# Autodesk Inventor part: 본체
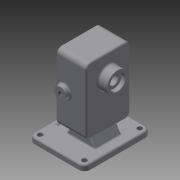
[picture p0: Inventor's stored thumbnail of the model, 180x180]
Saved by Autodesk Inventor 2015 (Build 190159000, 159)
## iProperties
Created: 2020-04
Part Number: 본체
Material: 일반
Document SubType Name: Modeling
Designer: CAD-08
Density: 1 g/cm^3
Appearance: 기본값
Author: CAD-08
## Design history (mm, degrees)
sketch "스케치1"
  geometry: L1 (50, -60)-(-50, -60); L2 (-50, -60)-(-50, 60); L3 (-50, 60)-(50, 60); L4 (50, 60)-(50, -60); L5 (50, -60)-(-50, 60); L6 (-50, -60)-(50, 60); 1 further point
  constraints: 12 end point, 2 midpoint, 2 parallel, 1 horizontal, 1 perpendicular
  dimensions: "d0" = 100 distance of L2.end L3.end; "d1" = 120 distance of L1.end L2.end
extrude "돌출1" new body sketch "스케치1" distance "d2" = 10; taper "d3" = 0 deg
fillet "모깎기1" dims "d4" = 10
sketch "스케치2"
  geometry: A1 r 10 centre (-40, 50) between (-40, 60) and (-50, 50) reference; A2 r 10 centre (-40, -50) between (-50, -50) and (-40, -60) reference; A3 r 10 centre (40, -50) between (40, -60) and (50, -50) reference; A4 r 10 centre (40, 50) between (50, 50) and (40, 60) reference; 1 further point
hole "구멍1" sketch "스케치2" at (-40, -50), (-40, 50), (40, -50), (40, 50) diameter "d5" = 9; stored, may be unused: countersink angle "d9" = 90 deg, drill point angle "d11" = 118 deg; dims "d6" = 6, "d7" = 4, "d8" = 2, "d10" = 8
sketch "스케치3"
  geometry: L1 (50, -50)-(50, 50) reference; L2 (-20, 24)-(33, 24); L3 (33, 24)-(33, -24); L4 (33, -24)-(-20, -24); L5 (-20, -24)-(-20, 24); L6 (0, 0)-(-20, 0)
  constraints: 10 end point, 2 horizontal, 2 parallel, 1 midpoint, 1 perpendicular, 1 other
  dimensions: "d12" = 48 distance of L4.end L2.start; "d13" = 53 distance of L3.end L4.end; "d14" = 17 distance between parallel lines of L1 L3
extrude "돌출2" join sketch "스케치3" distance "d15" = 50; taper "d16" = 0 deg
feature "면 기울기1" dims angle "d17" = 30 deg
feature "면 기울기2" dims angle "d18" = 30 deg
sketch "스케치5"
  geometry: L1 (-33, 10)-(-6.5, 55.899) reference; L2 (-6.5, 55.899)-(20, 10) reference; L3 (20, 10)-(50, 10) reference; L4 (50, 10)-(50, 0) reference; L5 (50, 0)-(-50, 0) reference; L6 (-50, 0)-(-50, 10) reference; L7 (-50, 10)-(-33, 10) reference; L8 (20, 30)-(-33, 30); L9 (-33, 30)-(-33, 150); L10 (-33, 150)-(20, 150); L11 (20, 150)-(20, 30); L12 (-6.5, 55.899)-(-6.5, 30); 1 further point
  constraints: 10 end point, 2 parallel, 1 horizontal, 1 midpoint, 1 perpendicular, 1 vertical, 1 other
  dimensions: "d26" = 120 distance of L10.end L8.start; "d27" = 53 distance of L9.end L10.end; "d28" = 150 distance between parallel lines of L5 L10
extrude "돌출4" join sketch "스케치5" stored distance "d29" = 80; taper "d30" = 0 deg
fillet "모깎기2" dims "d31" = 9
sketch "스케치7"
  geometry: A1 r 9 centre (9, 62) between (9, 71) and (0, 62) reference; A2 r 9 centre (9, 0) between (0, 0) and (9, -9) reference; A3 r 9 centre (111, 0) between (111, -9) and (120, 0) reference; A4 r 9 centre (111, 62) between (120, 62) and (111, 71) reference; 1 further point
hole "구멍2" sketch "스케치7" at (111, 62), (111, 0), (9, 62), (9, 0) diameter "d37" = 4.134; stored, may be unused: countersink angle "d41" = 90 deg, drill point angle "d43" = 118 deg; dims "d38" = 10, "d39" = 4, "d40" = 2, "d42" = 12
sketch "스케치8"
  geometry: C1 r 2.067 at (111, 62) reference; 2 further points
  constraints: 1 horizontal alignment
  dimensions: "d44" = 29 distance of C1.centre point (82, 62)
hole "구멍3" sketch "스케치8" at (82, 62) diameter "d45" = 4.134; stored, may be unused: countersink angle "d49" = 90 deg, drill point angle "d51" = 118 deg; dims "d46" = 10, "d47" = 4, "d48" = 2, "d50" = 12
sketch "스케치9"
  geometry: C1 r 2.067 at (9, 62) reference; 2 further points
  constraints: 1 horizontal alignment
  dimensions: "d52" = 29 distance of C1.centre point (38, 62)
hole "구멍4" sketch "스케치9" at (38, 62) diameter "d53" = 4.134; stored, may be unused: countersink angle "d57" = 90 deg, drill point angle "d59" = 118 deg; dims "d54" = 10, "d55" = 4, "d56" = 2, "d58" = 12
sketch "스케치12"
  geometry: L1 (9, 71)-(111, 71) reference; L2 (14, 31)-(106, 31); L3 (38, 7)-(82, 7); L4 (82, 55)-(38, 55); L5 (-30, -19)-(-30, 81) reference; A1 r 24 centre (38, 31) between (38, 55) and (38, 7); A2 r 24 centre (82, 31) between (82, 7) and (82, 55); 4 further points
  constraints: 8 end point, 6 point on circle, 4 tangent, 3 midpoint, 2 centre point, 2 point on line, 1 horizontal, 1 horizontal alignment, 1 parallel, 1 vertical alignment
  dimensions: "d71" = 24 radius of A2; "d72" = 92 distance of L2.start L2.end
extrude "돌출7" cut sketch "스케치12" distance "d73" = 29; taper "d74" = 0 deg
sketch "스케치13"
  geometry: L1 (-20, 141)-(-20, 39) reference; L2 (40, 0)-(-40, 0) reference; C1 r 11 at (-6, 90); 1 further point
  constraints: 1 centre point
  dimensions: "d75" = 22 diameter of C1; "d76" = 14 distance from line of L1 C1.centre; "d77" = 90 distance from line of L2 C1.centre
extrude "돌출8" join sketch "스케치13" distance "d78" = 8; taper "d79" = 0 deg
sketch "스케치14"
  geometry: C1 r 11 at (0, 0) reference; 1 further point
hole "구멍6" sketch "스케치14" at (0, 0) diameter "d80" = 8.376; stored, may be unused: countersink angle "d84" = 90 deg, drill point angle "d86" = 118 deg; dims "d81" = 20, "d82" = 4, "d83" = 2, "d85" = 27.3
sketch "스케치15"
  geometry: C1 r 12.5 at (82, 31); A1 r 24 centre (82, 31) between (82, 7) and (82, 55) reference; 1 further point
  constraints: 1 centre point, 1 coincident
  dimensions: "d87" = 25 diameter of C1
extrude "돌출9" cut sketch "스케치15" distance "d88" = 15; taper "d89" = 0 deg
sketch "스케치16"
  geometry: C1 r 12.5 at (38, 31); A1 r 24 centre (38, 31) between (38, 55) and (38, 7) reference; 1 further point
  constraints: 1 centre point, 1 coincident
  dimensions: "d90" = 25 diameter of C1
extrude "돌출10" cut sketch "스케치16" distance "d91" = 15; taper "d92" = 0 deg
sketch "스케치17"
  geometry: C1 r 12.5 at (0, 0) reference; C2 r 8.5 at (0, 0); 1 further point
  constraints: 1 centre point, 1 coincident
  dimensions: "d93" = 17 diameter of C2
extrude "돌출11" cut sketch "스케치17" stored distance "d94" = 15; taper "d95" = 0 deg
sketch "스케치18"
  geometry: C1 r 8.5 at (38, 31) reference; C2 r 19 at (38, 31); 1 further point
  constraints: 1 centre point, 1 coincident
  dimensions: "d96" = 38 diameter of C2
extrude "돌출12" join sketch "스케치18" distance "d97" = 17; taper "d98" = 0 deg
sketch "스케치19"
  geometry: C1 r 8.5 at (0, 0) reference; C2 r 19 at (0, 0) reference; C3 r 14 at (0, 0); 1 further point
  constraints: 1 centre point, 1 coincident
  dimensions: "d99" = 28 diameter of C3
extrude "돌출13" cut sketch "스케치19" distance "d100" = 7.3; taper "d101" = 0 deg
chamfer "모따기1" distance "d102" = 0.7; stored, may be unused: second distance "d103" = 2, angle "d104" = 30 deg
fillet "모깎기3" dims "d105" = 0.5
fillet "모깎기4" dims "d106" = 3
fillet "모깎기5" dims "d107" = 3
fillet "모깎기6" dims "d108" = 3
fillet "모깎기7" dims "d109" = 3
fillet "모깎기8" dims "d110" = 3
fillet "모깎기9" dims "d111" = 3
chamfer "모따기2" distance "d112" = 1; stored, may be unused: second distance "d113" = 2, angle "d114" = 30 deg
sketch "스케치20"
  geometry: L1 (40, 60)-(-40, 60) reference; L2 (-50, 50)-(-50, -50) reference; 2 further points
  constraints: 1 other
  dimensions: "d115" = 60 distance from line of point (-40, 0) L1; "d116" = 10 distance from line of L2 point (-40, 0)
feature "엠보싱1" sketch "스케치20" dims "d117" = 1, "d118" = 0
node "솔리드1"
mirror "대칭1"
mirror "대칭2"
mirror "대칭4"
node "절단 모서리 투영2"
